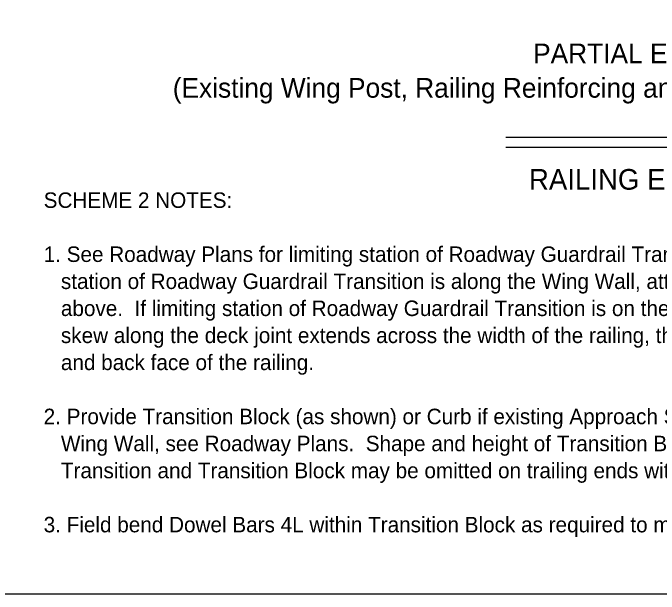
# Model space of a CAD drawing. Extents: x 1.5 to 68.7, y 0 to 31.
# Drawn here: x 20.46 to 28.88, y 1.78 to 9.35 of the extents above; entities that cross this region are included whole.
import ezdxf

# ---------------------------------------------------------------- set-up
doc = ezdxf.new("R2010")
doc.units = 0
doc.layers.add('ActivePts-ConstElements', color=7, linetype='Continuous')
doc.layers.add('AdhocPoint_dp', color=7, linetype='Continuous')

msp = doc.modelspace()

# ---------------------------------------------------------------- linework, layer by layer
at = {"layer": 'ActivePts-ConstElements'}
msp.add_lwpolyline([(1.4667, 28.1828), (42.5333, 28.1828), (42.5333, 1.7828), (1.4667, 1.7828)], close=True, dxfattribs=at)
at = {"layer": 'AdhocPoint_dp'}
for p, q in [((30.8711, 7.7273), (26.882, 7.7273)), ((30.8711, 7.5974), (26.882, 7.5974))]:
    msp.add_line(p, q, dxfattribs=at)

# ---------------------------------------------------------------- texts
for s, height, p in [('PARTIAL ELEVATION OF INSIDE FACE OF RAILING', 0.256001, (27.2388, 8.6931)), ('(Existing Wing Post, Railing Reinforcing and Expansion Dowel Assemblies not shown for clarity)', 0.256001, (22.5449, 8.2451)), ('RAILING END TREATMENT FOR PARALLEL CURBS', 0.268801, (27.1845, 7.0476)), ('SCHEME 2 NOTES:', 0.2016, (20.8632, 6.8105)), ('1. See Roadway Plans for limiting station of Roadway Guardrail Transition or other site specific treatment.  If limiting', 0.2016004, (20.8632, 6.1065)), ('   station of Roadway Guardrail Transition is along the Wing Wall, attach Thrie-Beam Terminal Connector to railing as shown', 0.2016004, (20.8632, 5.7545)), ('   above.  If limiting station of Roadway Guardrail Transition is on the bridge, see Sheet 3 of 6.  On skewed bridges, if the', 0.2016004, (20.8632, 5.4025)), ('   skew along the deck joint extends across the width of the railing, the 2\'-6" minimum dimension shall apply to both the front ', 0.2016004, (20.8632, 5.0505)), ('   and back face of the railing.', 0.2016, (20.8632, 4.6985)), ('2. Provide Transition Block (as shown) or Curb if existing Approach Slab Curb does not extend beyond end of existing End Bent ', 0.2016004, (20.8632, 3.9945)), ('   Wing Wall, see Roadway Plans.  Shape and height of Transition Block or Curb shall match existing bridge curb.  Railing End ', 0.2016004, (20.8632, 3.6425)), ('   Transition and Transition Block may be omitted on trailing ends with no opposing traffic.', 0.2016, (20.8632, 3.2905)), ('3. Field bend Dowel Bars 4L within Transition Block as required to maintain 2" top and side clearance and 3" bottom clearance.', 0.2016004, (20.8632, 2.5865))]:
    msp.add_text(s, height=height, dxfattribs=at).set_placement(p)

doc.saveas('drawing.dxf')
